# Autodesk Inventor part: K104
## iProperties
Author: Administrator
Revision Number: A
Shininess: 41.0
PropertySet Name: _Private Model Information
Created: 2000-11
Part Number: K104
Project: ACME
Description: KNOB, .375 DIA
Document SubType Name: Modeling
Designer: E. MOSS
Control State: 0
Master: False
Checked Out: False
PropertySet Name: Design Tracking Control
Density: 0.0
Volumn: 0.0
Area: 0.0
PropertySet Name: Model Information
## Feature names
1. Revolution1
2. Revolution2
3. Fillet1
